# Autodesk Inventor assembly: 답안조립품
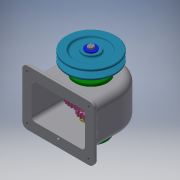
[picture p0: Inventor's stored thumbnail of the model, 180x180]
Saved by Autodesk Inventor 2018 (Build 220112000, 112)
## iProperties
Created: 2022-09
Part Number: 답안조립품
Material: 일반
Document SubType Name: Assembly
Designer: home
Author: home
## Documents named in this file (15)
- C:\Users\kimgi\Desktop\720906V1014\답안조립품.iam
- C:\Users\kimgi\Desktop\720906V1014\본체.ipt
- C:\Users\kimgi\Desktop\720906V1014\뒤커버.ipt
- C:\Users\kimgi\Desktop\720906V1014\앞커버.ipt
- C:\Users\kimgi\Desktop\720906V1014\축.ipt
- C:\Users\kimgi\Desktop\720906V1014\베어링 6203.ipt
- C:\Users\kimgi\Desktop\720906V1014\키 6 x 6 x 22.ipt
- C:\Users\kimgi\Desktop\720906V1014\키 5 x 5 x 18.ipt
- C:\Users\kimgi\Desktop\720906V1014\스퍼기어.ipt
- C:\Users\kimgi\Desktop\720906V1014\칼라.ipt
- C:\Users\kimgi\Desktop\720906V1014\볼트 M3 x 10.ipt
- C:\Users\kimgi\Desktop\720906V1014\V-벨트풀리.ipt
- C:\Users\kimgi\Desktop\720906V1014\와셔 6 x 22.ipt
- C:\Users\kimgi\Desktop\720906V1014\육각머리볼트 M3 x 8.ipt
- C:\Users\kimgi\Desktop\720906V1014\멈춤나사 M4 x 10.ipt
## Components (9 placed, 2 different names)
1. V-벨트풀리:1
2. ISO 4762 M3 x 10:1
3. ISO 4762 M3 x 10:3
4. ISO 4762 M3 x 10:4
5. ISO 4762 M3 x 10:5
6. ISO 4762 M3 x 10:2
7. ISO 4762 M3 x 10:6
8. ISO 4762 M3 x 10:7
9. ISO 4762 M3 x 10:8
